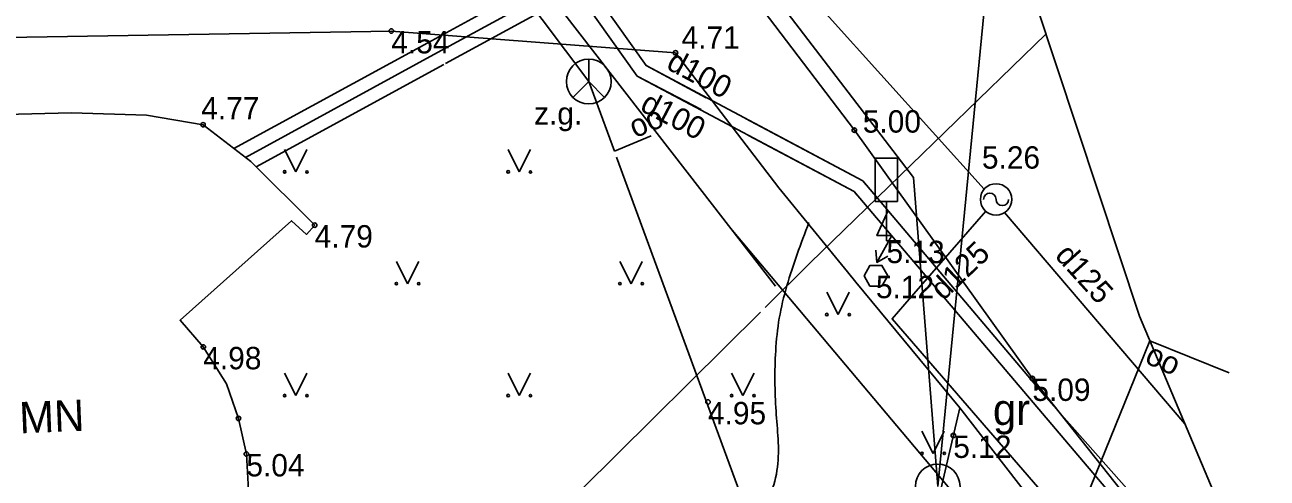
# Model space of a CAD drawing. Extents: x 519536 to 519949, y 326041 to 326519.
# Drawn here: x 519856.44 to 519884.23, y 326180.65 to 326190.79 of the extents above; entities that cross this region are included whole.
import ezdxf

# ---------------------------------------------------------------- set-up
doc = ezdxf.new("R2010")
doc.units = 0
for name, color, linetype in [('APGR_ELEM_####_####_#', 7, 'Continuous'), ('APGR_SARK_####_####_#', 7, 'Continuous'), ('BUVE_EKAS_####_####_#', 7, 'Continuous'), ('BUVE_EKAS_RAKS_TKST_#', 7, 'Continuous'), ('CELI_CMAL_####_####_#', 7, 'Continuous'), ('CELI_CSEG_####_TKST_#', 7, 'Continuous'), ('CELI_ELEM_####_####_#', 7, 'Continuous'), ('CELI_SEGL_####_####_#', 7, 'Continuous'), ('CKOM_ELEM_####_####_#', 7, 'Continuous'), ('ELEK_ACRL_####_####_#', 7, 'Continuous'), ('ELEK_ACRL_####_TKST_#', 7, 'Continuous'), ('ELEK_VADP_ZSPR_####_#', 7, 'Continuous'), ('GAZE_ELEM_####_####_#', 7, 'Continuous'), ('GAZE_ELEM_####_TKST_#', 7, 'Continuous'), ('GAZE_VADP_VSP2_####_#', 7, 'Continuous'), ('GAZE_VADP_VSP2_TKST_#', 7, 'Continuous'), ('RAMI_UZMR_####_####_#', 7, 'Continuous'), ('RELJ_AATZ_####_TKST_#', 7, 'Continuous'), ('RELJ_ELEM_####_####_#', 7, 'Continuous'), ('RELJ_HORZ_PAMT_####_#', 7, 'Continuous'), ('ROBZ_PROJ_####_####_#', 7, 'Continuous'), ('ROBZ_UZMR_####_####_#', 7, 'Continuous'), ('SAKK_ELEM_####_####_#', 7, 'Continuous'), ('SAKK_ELEM_####_TKST_#', 7, 'Continuous'), ('SAKK_IZVK_####_TKST_#', 7, 'Continuous'), ('SAKK_KKAN_####_####_#', 7, 'Continuous'), ('SAKT_VADP_NEDR_####_#', 7, 'Continuous'), ('TERT_ELEM_####_####_#', 7, 'Continuous'), ('UDTK_VADP_UDEN_####_#', 7, 'Continuous')]:
    doc.layers.add(name, color=color, linetype=linetype)

msp = doc.modelspace()

# ---------------------------------------------------------------- linework, layer by layer
at = {"layer": 'APGR_ELEM_####_####_#'}
msp.add_circle((519876.86, 326180.47), 0.5, dxfattribs=at)
at = {"layer": 'APGR_SARK_####_####_#'}
msp.add_line((519877.92, 326191.345), (519876.86, 326180.47), dxfattribs=at)
at = {"layer": 'BUVE_EKAS_####_####_#'}
msp.add_line((519861.445, 326180.383), (519861.394, 326181.193), dxfattribs=at)
for points in [[(519860.426, 326188.553), (519859.163, 326188.764), (519857.483, 326188.82), (519854.509, 326188.745)], [(519860.426, 326188.553), (519861.496, 326187.731), (519862.923, 326186.309), (519862.737, 326186.102), (519862.406, 326186.406), (519859.913, 326184.183), (519860.43, 326183.587)], [(519861.394, 326181.193), (519861.218, 326181.989), (519860.948, 326182.759), (519860.43, 326183.587)]]:
    msp.add_lwpolyline(points, dxfattribs=at)
at = {"layer": 'CELI_CMAL_####_####_#'}
msp.add_line((519875.029, 326185.038), (519877.351, 326182.225), dxfattribs=at)
for points in [[(519882.222, 326178.789), (519878.977, 326182.88), (519874.995, 326188.433), (519867.888, 326197.765), (519858.139, 326210.779), (519849.58, 326222.15), (519841.494, 326233.418), (519836.895, 326239.916), (519835.264, 326243.212)], [(519787.061, 326208.66), (519797.129, 326204.029), (519817.623, 326196.632), (519829.055, 326193.272), (519842.621, 326190.678), (519855.118, 326190.491), (519864.636, 326190.648), (519870.995, 326190.162)], [(519874.844, 326185.262), (519873.303, 326187.141), (519870.995, 326190.162)], [(519874.844, 326185.262), (519875.029, 326185.038)], [(519877.351, 326182.225), (519876.372, 326177.998), (519873.083, 326173.06)]]:
    msp.add_lwpolyline(points, dxfattribs=at)
at = {"layer": 'CELI_ELEM_####_####_#'}
for p, q in [((519875.96, 326187.807), (519875.46, 326187.807)), ((519875.46, 326186.838), (519875.46, 326187.807)), ((519875.96, 326186.838), (519875.96, 326187.807)), ((519875.96, 326186.838), (519875.46, 326186.838)), ((519875.714, 326186.838), (519875.714, 326185.96)), ((519875.714, 326185.96), (519876.029, 326185.96))]:
    msp.add_line(p, q, dxfattribs=at)
at = {"layer": 'CELI_SEGL_####_####_#'}
msp.add_lwpolyline([(519877.351, 326182.225), (519879.924, 326178.91)], dxfattribs=at)
at = {"layer": 'CKOM_ELEM_####_####_#'}
msp.add_line((519875.5, 326185.476), (519875.741, 326185.615), dxfattribs=at)
msp.add_lwpolyline([(519875.749, 326186.638), (519875.5, 326186.075), (519875.836, 326186.075), (519875.5, 326185.476), (519875.478, 326185.746)], dxfattribs=at)
msp.add_lwpolyline([(519875.344, 326184.946), (519875.61, 326184.946), (519875.743, 326185.176), (519875.61, 326185.407), (519875.344, 326185.407), (519875.211, 326185.176)], close=True, dxfattribs=at)
at = {"layer": 'ELEK_ACRL_####_####_#'}
for p, q in [((519870.337, 326189.874), (519871.68, 326189.158)), ((519870.133, 326189.642), (519871.57, 326188.891))]:
    msp.add_line(p, q, dxfattribs=at)
at = {"layer": 'ELEK_VADP_ZSPR_####_#'}
for points in [[(519875.255, 326187.215), (519875.182, 326187.301), (519870.337, 326189.874), (519865.693, 326196.404)], [(519875.053, 326186.989), (519874.99, 326187.063), (519870.133, 326189.642), (519865.422, 326196.266)], [(519871.589, 326187.061), (519864.724, 326195.91)], [(519872.559, 326188.693), (519875.181, 326187.3), (519879.283, 326182.454), (519882.424, 326178.919)], [(519882.13, 326178.73), (519881.246, 326179.694), (519874.989, 326187.062), (519872.629, 326188.316)], [(519873.23, 326184.946), (519871.589, 326187.061)], [(519872.258, 326186.198), (519879.625, 326177.451)]]:
    msp.add_lwpolyline(points, dxfattribs=at)
at = {"layer": 'GAZE_ELEM_####_####_#'}
msp.add_circle((519878.164, 326186.885), 0.35, dxfattribs=at)
for centre, start, end in [((519878.024, 326186.885), 0, 180), ((519878.304, 326186.885), 180, 0)]:
    msp.add_arc(centre, 0.14, start, end, dxfattribs=at)
at = {"layer": 'GAZE_VADP_VSP2_####_#'}
for points in [[(519873.273, 326192.249), (519877.901, 326187.116)], [(519876.124, 326184.544), (519877.934, 326186.621)], [(519878.351, 326186.589), (519882.385, 326181.871)], [(519881.32, 326178.21), (519879.918, 326179.555), (519879.676, 326179.787), (519875.839, 326184.216), (519876.124, 326184.544)]]:
    msp.add_lwpolyline(points, dxfattribs=at)
at = {"layer": 'RAMI_UZMR_####_####_#'}
msp.add_lwpolyline([(519873.021, 326209.453), (519881.37, 326184.273), (519884.229, 326177.508), (519883.353, 326172.044), (519868.284, 326155.201), (519831.787, 326123.789), (519817.117, 326113.183), (519808.359, 326108.08), (519804.649, 326107.204), (519795.685, 326122.565), (519782.956, 326146.875), (519761.4, 326134.85), (519741.243, 326123.664), (519728.435, 326146.148), (519720.513, 326144.604), (519669.064, 326119.018)], dxfattribs=at)
at = {"layer": 'RELJ_ELEM_####_####_#'}
for centre in [(519864.636, 326190.648), (519870.995, 326190.162), (519860.426, 326188.553), (519874.995, 326188.433), (519862.923, 326186.309), (519860.43, 326183.587), (519878.977, 326182.88), (519871.72, 326182.357), (519861.218, 326181.989), (519877.208, 326181.606), (519861.394, 326181.193)]:
    msp.add_circle(centre, 0.05, dxfattribs=at)
at = {"layer": 'RELJ_HORZ_PAMT_####_#'}
msp.add_spline([(519868.771, 326176.513), (519869.962, 326177.426), (519871.589, 326178.798), (519872.684, 326179.748), (519872.912, 326179.993), (519873.009, 326180.132), (519873.098, 326180.283), (519873.275, 326180.902), (519873.243, 326182.152), (519873.235, 326183.496), (519873.315, 326184.23), (519873.486, 326184.949), (519873.717, 326185.66), (519873.976, 326186.366)], degree=3, dxfattribs=at)
at = {"layer": 'ROBZ_PROJ_####_####_#'}
for p, q in [((519876.321, 326187.374), (519841.088, 326233.318)), ((519876.86, 326180.47), (519876.321, 326187.374))]:
    msp.add_line(p, q, dxfattribs=at)
at = {"layer": 'ROBZ_UZMR_####_####_#'}
for p, q in [((519841.088, 326233.318), (519876.321, 326187.374)), ((519876.321, 326187.374), (519876.86, 326180.47))]:
    msp.add_line(p, q, dxfattribs=at)
at = {"layer": 'SAKK_ELEM_####_####_#'}
msp.add_line((519869.054, 326189.519), (519869.408, 326189.165), dxfattribs=at)
msp.add_lwpolyline([(519869.054, 326190.019), (519869.054, 326189.519), (519868.7, 326189.165)], dxfattribs=at)
msp.add_circle((519869.054, 326189.519), 0.5, dxfattribs=at)
at = {"layer": 'SAKK_IZVK_####_TKST_#'}
msp.add_line((519869.628, 326187.96), (519870.451, 326188.303), dxfattribs=at)
msp.add_lwpolyline([(519881.601, 326183.726), (519883.382, 326183.007)], dxfattribs=at)
at = {"layer": 'SAKK_KKAN_####_####_#'}
for points in [[(519864.377, 326195.733), (519869.054, 326189.519), (519869.628, 326187.96)], [(519869.677, 326187.826), (519873.048, 326178.67), (519873.513, 326178.196)], [(519880.279, 326180.451), (519881.601, 326183.726)]]:
    msp.add_lwpolyline(points, dxfattribs=at)
at = {"layer": 'SAKT_VADP_NEDR_####_#'}
for p, q in [((519865.532, 326190.43), (519877.216, 326196.8)), ((519865.673, 326190.165), (519877.313, 326196.508)), ((519865.848, 326189.919), (519877.407, 326196.226)), ((519861.117, 326188.022), (519865.532, 326190.43)), ((519861.377, 326187.823), (519865.673, 326190.165)), ((519861.616, 326187.611), (519865.814, 326189.9))]:
    msp.add_line(p, q, dxfattribs=at)
at = {"layer": 'TERT_ELEM_####_####_#'}
for p, q in [((519862.25, 326188), (519862.5, 326187.5)), ((519862.5, 326187.5), (519862.75, 326188)), ((519867.25, 326188), (519867.5, 326187.5)), ((519867.5, 326187.5), (519867.75, 326188)), ((519864.75, 326185.5), (519865, 326185)), ((519865, 326185), (519865.25, 326185.5)), ((519869.75, 326185.5), (519870, 326185)), ((519870, 326185), (519870.25, 326185.5)), ((519874.38, 326184.81), (519874.63, 326184.31)), ((519874.63, 326184.31), (519874.88, 326184.81)), ((519862.25, 326183), (519862.5, 326182.5)), ((519862.5, 326182.5), (519862.75, 326183)), ((519867.25, 326183), (519867.5, 326182.5)), ((519867.5, 326182.5), (519867.75, 326183)), ((519872.25, 326183), (519872.5, 326182.5)), ((519872.5, 326182.5), (519872.75, 326183)), ((519876.507, 326181.707), (519876.757, 326181.207)), ((519876.757, 326181.207), (519877.007, 326181.707))]:
    msp.add_line(p, q, dxfattribs=at)
for centre, radius in [((519862.25, 326187.5), 0.028), ((519862.75, 326187.5), 0.0263), ((519867.25, 326187.5), 0.028), ((519867.75, 326187.5), 0.0263), ((519864.75, 326185), 0.028), ((519865.25, 326185), 0.0263), ((519869.75, 326185), 0.028), ((519870.25, 326185), 0.0263), ((519874.38, 326184.31), 0.028), ((519874.88, 326184.31), 0.0263), ((519862.25, 326182.5), 0.028), ((519862.75, 326182.5), 0.0263), ((519867.25, 326182.5), 0.028), ((519867.75, 326182.5), 0.0263), ((519872.25, 326182.5), 0.028), ((519872.75, 326182.5), 0.0263), ((519876.507, 326181.207), 0.028), ((519877.007, 326181.207), 0.0263)]:
    msp.add_circle(centre, radius, dxfattribs=at)
at = {"layer": 'UDTK_VADP_UDEN_####_#'}
for p, q in [((519874.009, 326185.465), (519879.281, 326190.575)), ((519868.894, 326180.401), (519872.896, 326184.362))]:
    msp.add_line(p, q, dxfattribs=at)
msp.add_lwpolyline([(519873.003, 326184.469), (519874.009, 326185.465)], dxfattribs=at)

# ---------------------------------------------------------------- texts
at = {"layer": 'BUVE_EKAS_RAKS_TKST_#'}
msp.add_text('MN', height=0.7, rotation=2.3522, dxfattribs=at).set_placement((519856.327, 326181.654))
at = {"layer": 'CELI_CSEG_####_TKST_#'}
msp.add_text('gr', height=0.7, dxfattribs=at).set_placement((519878.095, 326181.839))
at = {"layer": 'ELEK_ACRL_####_TKST_#'}
for rotation, p in [(331.9364, (519870.762, 326189.818)), (332.4077, (519870.174, 326188.884))]:
    msp.add_text('d100', height=0.5, rotation=rotation, dxfattribs=at).set_placement(p)
at = {"layer": 'GAZE_ELEM_####_TKST_#'}
msp.add_text('5.26', height=0.5, dxfattribs=at).set_placement((519877.848, 326187.572))
at = {"layer": 'GAZE_VADP_VSP2_TKST_#'}
for rotation, p in [(43.5388, (519876.984, 326184.606)), (312.074, (519879.461, 326185.613))]:
    msp.add_text('d125', height=0.5, rotation=rotation, dxfattribs=at).set_placement(p)
at = {"layer": 'RELJ_AATZ_####_TKST_#'}
for s, p in [('4.54', (519864.636, 326190.148)), ('4.71', (519871.128, 326190.25)), ('4.77', (519860.383, 326188.671)), ('5.00', (519875.183, 326188.377)), ('4.79', (519862.923, 326185.809)), ('5.13', (519875.714, 326185.46)), ('5.12', (519875.477, 326184.676)), ('4.98', (519860.43, 326183.087)), ('5.09', (519878.977, 326182.38)), ('4.95', (519871.72, 326181.857)), ('5.12', (519877.208, 326181.106)), ('5.04', (519861.394, 326180.693))]:
    msp.add_text(s, height=0.5, dxfattribs=at).set_placement(p)
at = {"layer": 'SAKK_ELEM_####_TKST_#'}
msp.add_text('z.g.', height=0.5, dxfattribs=at).set_placement((519867.83, 326188.556))
at = {"layer": 'SAKK_IZVK_####_TKST_#'}
for rotation, p in [(22.6249, (519870.087, 326188.249)), (155.2157, (519882.303, 326183.281))]:
    msp.add_text('oo', height=0.5, rotation=rotation, dxfattribs=at).set_placement(p)

doc.saveas('drawing.dxf')
